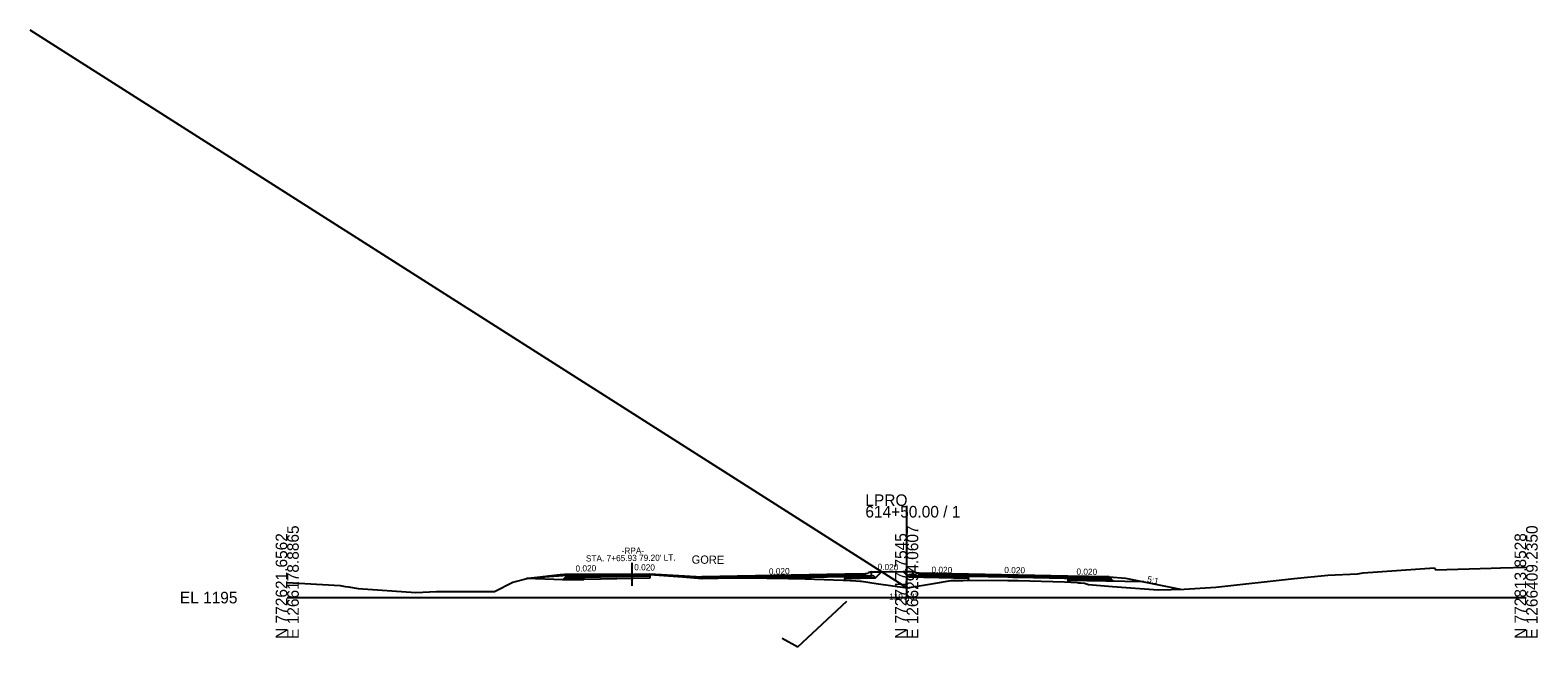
# Model space of a CAD drawing. Extents: x -3833 to 1267678, y -522 to 773248.
# Drawn here: x 1937.8 to 2302.8, y 5488.1 to 5637.4 of the extents above; entities that cross this region are included whole.
import ezdxf

# ---------------------------------------------------------------- set-up
doc = ezdxf.new("R2010")
doc.units = 0
for name, color, linetype in [('Exist Cross Section Cell', 7, 'Continuous'), ('Exist XS Center Line Elevation Label', 7, 'Continuous'), ('Exist XS Ground Line', 7, 'Continuous'), ('Prop CMT Corridor Surface Symbology Green', 7, 'Continuous'), ('Prop CMT DNC', 7, 'Continuous'), ('Prop CMT Pvmt Course 1', 7, 'Continuous'), ('Prop CMT Pvmt Course 2', 7, 'Continuous'), ('Prop CMT Pvmt Course 3', 7, 'Continuous'), ('Prop CMT Pvmt Course 4', 7, 'Continuous'), ('Prop CMT Shld Paved Course 1', 7, 'Continuous'), ('Prop CMT Shld Paved Course 2', 7, 'Continuous'), ('Prop CMT Shld Paved Course 4', 7, 'Continuous'), ('Prop CMT Slope Grass', 7, 'Continuous'), ('Prop CMT Subgrade Earthwork', 7, 'Continuous'), ('Prop Conc Curb and Gutter', 7, 'Continuous'), ('Prop Conc Island Cover', 7, 'Continuous'), ('Prop Corridor Mesh Bottom', 7, 'Continuous'), ('Prop XS Ditch Slope Text', 7, 'Continuous'), ('Prop XS Finish Grade', 7, 'Continuous'), ('Prop XS SE Text', 7, 'Continuous'), ('Prop XS Shear Point Element', 7, 'Continuous'), ('Prop XS Shear Point Label', 7, 'Continuous'), ('Scratch_Level_1', 7, 'Continuous'), ('Scratch_Level_5', 7, 'Continuous')]:
    doc.layers.add(name, color=color, linetype=linetype)

msp = doc.modelspace()

# ---------------------------------------------------------------- linework, layer by layer
at = {"layer": 'Exist Cross Section Cell'}
for p, q in [((2150, 5500), (2150, 5522.2)), ((2000, 5500), (2150, 5500)), ((2150, 5500), (2300, 5500))]:
    msp.add_line(p, q, dxfattribs=at)
at = {"layer": 'Exist XS Ground Line'}
for p, q in [((2058.41, 5504.72), (2066.11, 5505.59)), ((2066.11, 5505.59), (2067.15, 5505.7)), ((2067.15, 5505.7), (2073.18, 5505.68)), ((2073.18, 5505.68), (2083.57, 5505.64)), ((2083.57, 5505.64), (2086.45, 5505.51)), ((2087.18, 5505.49), (2087.86, 5505.61)), ((2087.86, 5505.61), (2088.94, 5505.52)), ((2252.01, 5505.42), (2259.15, 5505.75)), ((2259.15, 5505.75), (2260.55, 5505.96)), ((2260.55, 5505.96), (2277.79, 5507.22)), ((2277.79, 5507.22), (2278.16, 5506.71)), ((2278.16, 5506.71), (2291.56, 5507.14)), ((2291.56, 5507.14), (2293.8, 5507.21)), ((2293.8, 5507.21), (2300, 5507.4)), ((2000, 5503.66), (2012.83, 5502.97)), ((2012.83, 5502.97), (2014.07, 5502.67)), ((2014.07, 5502.67), (2014.8, 5502.62)), ((2014.8, 5502.62), (2017.17, 5502.19)), ((2017.17, 5502.19), (2031.11, 5501.2)), ((2050.17, 5501.49), (2054.61, 5503.71)), ((2054.61, 5503.71), (2058.41, 5504.72)), ((2086.45, 5505.51), (2087.18, 5505.49)), ((2088.94, 5505.52), (2095.68, 5505.01)), ((2095.68, 5505.01), (2100.49, 5504.63)), ((2100.49, 5504.63), (2108.21, 5504.78)), ((2108.21, 5504.78), (2111.02, 5504.82)), ((2111.02, 5504.82), (2121.35, 5504.62)), ((2121.35, 5504.62), (2123.05, 5504.6)), ((2123.05, 5504.6), (2134.66, 5504.19)), ((2134.66, 5504.19), (2136.33, 5504.13)), ((2136.33, 5504.13), (2136.67, 5504.11)), ((2136.67, 5504.11), (2138.74, 5504)), ((2138.74, 5504), (2139.09, 5503.95)), ((2139.09, 5503.95), (2142.64, 5503.44)), ((2142.64, 5503.44), (2150.11, 5502.36)), ((2150.11, 5502.36), (2156.95, 5503.51)), ((2156.95, 5503.51), (2160.27, 5504.05)), ((2160.27, 5504.05), (2160.75, 5504.14)), ((2160.75, 5504.14), (2163.68, 5504.18)), ((2163.68, 5504.18), (2164.03, 5504.19)), ((2164.03, 5504.19), (2174.51, 5504.16)), ((2174.51, 5504.16), (2175.71, 5504.15)), ((2175.71, 5504.15), (2176.99, 5504.11)), ((2176.99, 5504.11), (2188.24, 5503.79)), ((2188.24, 5503.79), (2191.31, 5503.62)), ((2191.31, 5503.62), (2191.64, 5503.59)), ((2191.64, 5503.59), (2192.12, 5503.56)), ((2192.12, 5503.56), (2193.04, 5503.46)), ((2193.04, 5503.46), (2194.01, 5503.16)), ((2194.01, 5503.16), (2199.82, 5502.72)), ((2199.82, 5502.72), (2210.9, 5501.85)), ((2210.9, 5501.85), (2217.18, 5502.05)), ((2217.18, 5502.05), (2224.87, 5502.53)), ((2224.87, 5502.53), (2243.83, 5504.65)), ((2243.83, 5504.65), (2252.01, 5505.42)), ((2031.11, 5501.2), (2036.18, 5501.45)), ((2036.18, 5501.45), (2050.17, 5501.49))]:
    msp.add_line(p, q, dxfattribs=at)
at = {"layer": 'Prop CMT Pvmt Course 1'}
for p, q in [((2071.83, 5505.46), (2083.83, 5505.7)), ((2083.83, 5505.7), (2087.83, 5505.78)), ((2083.83, 5505.7), (2083.83, 5505.7)), ((2087.83, 5505.53), (2083.83, 5505.45)), ((2087.83, 5505.78), (2100.42, 5505)), ((2087.83, 5505.78), (2087.83, 5505.53)), ((2087.83, 5505.78), (2087.83, 5505.78)), ((2087.83, 5505.78), (2087.83, 5505.78)), ((2087.83, 5505.53), (2087.83, 5505.53)), ((2135, 5505.69), (2100.42, 5505)), ((2135, 5505.44), (2135, 5505.69)), ((2189, 5505.21), (2165, 5505.69)), ((2165, 5505.69), (2165, 5505.44)), ((2071.83, 5505.21), (2071.83, 5505.46)), ((2071.83, 5505.46), (2071.83, 5505.46)), ((2083.83, 5505.45), (2071.83, 5505.21)), ((2083.83, 5505.45), (2083.83, 5505.45)), ((2100.42, 5504.75), (2135, 5505.44)), ((2100.42, 5505), (2100.42, 5505)), ((2100.42, 5505), (2100.42, 5504.75)), ((2100.42, 5504.75), (2100.42, 5504.75)), ((2135, 5505.44), (2135, 5505.44)), ((2165, 5505.44), (2165, 5505.44)), ((2165, 5505.44), (2189, 5504.96)), ((2189, 5504.96), (2189, 5505.21)), ((2189, 5505.21), (2189, 5505.21)), ((2189, 5504.96), (2189, 5504.96)), ((2189, 5504.96), (2189, 5504.96))]:
    msp.add_line(p, q, dxfattribs=at)
at = {"layer": 'Prop CMT Pvmt Course 2'}
for p, q in [((2083.83, 5505.45), (2087.83, 5505.53)), ((2087.83, 5505.53), (2087.83, 5505.28)), ((2087.83, 5505.53), (2087.83, 5505.53)), ((2087.83, 5505.53), (2087.83, 5505.53)), ((2087.84, 5505.6), (2100.42, 5504.75)), ((2139.96, 5505.54), (2135, 5505.44)), ((2165, 5505.44), (2153, 5505.68)), ((2071.83, 5505.21), (2083.83, 5505.45)), ((2071.83, 5504.96), (2071.83, 5505.21)), ((2071.83, 5505.21), (2071.83, 5505.21)), ((2083.83, 5505.45), (2083.83, 5505.45)), ((2083.83, 5505.2), (2083.83, 5505.2)), ((2087.83, 5505.2), (2083.84, 5505.12)), ((2087.83, 5505.28), (2087.83, 5505.28)), ((2135, 5505.44), (2135, 5505.44)), ((2135, 5505.44), (2135, 5505.11)), ((2135, 5505.1), (2139.96, 5505.2)), ((2135, 5505.11), (2135, 5505.11)), ((2135, 5505.11), (2135, 5505.1)), ((2135, 5505.1), (2135, 5505.1)), ((2153, 5505.35), (2165, 5505.1)), ((2165, 5505.44), (2165, 5505.44)), ((2165, 5505.1), (2165, 5505.1)), ((2165, 5505.1), (2165, 5505.1)), ((2165, 5505.1), (2165, 5505.1))]:
    msp.add_line(p, q, dxfattribs=at)
at = {"layer": 'Prop CMT Pvmt Course 3'}
for p, q in [((2141.97, 5505.24), (2139.96, 5505.2)), ((2139.96, 5505.2), (2139.96, 5505.2)), ((2142.42, 5504.8), (2141.97, 5505.24)), ((2150.7, 5505.1), (2150.99, 5505.38))]:
    msp.add_line(p, q, dxfattribs=at)
at = {"layer": 'Prop CMT Pvmt Course 4'}
for p, q in [((2067.23, 5504.79), (2071.84, 5504.88)), ((2071.83, 5504.46), (2071.83, 5504.96)), ((2071.83, 5504.96), (2071.83, 5504.96)), ((2083.85, 5504.66), (2071.83, 5504.42)), ((2083.84, 5505.12), (2071.84, 5504.88)), ((2083.83, 5505.2), (2083.83, 5505.2)), ((2087.83, 5504.74), (2083.85, 5504.66)), ((2087.83, 5505.28), (2087.83, 5504.74)), ((2087.83, 5505.28), (2087.83, 5505.28)), ((2087.83, 5505.28), (2087.83, 5505.28)), ((2087.83, 5504.78), (2087.83, 5504.78)), ((2139.96, 5505.2), (2135, 5505.1)), ((2135, 5505.1), (2135, 5505.11)), ((2135, 5505.11), (2135, 5504.18)), ((2135, 5505.1), (2135, 5505.1)), ((2135, 5504.64), (2142.42, 5504.8)), ((2135, 5504.27), (2135, 5504.27)), ((2135, 5504.27), (2135, 5504.27)), ((2135, 5504.27), (2135, 5504.27)), ((2150.99, 5505.38), (2150.54, 5504.94)), ((2151.49, 5505.37), (2150.99, 5505.38)), ((2165, 5504.27), (2165, 5505.1)), ((2165, 5505.1), (2165, 5505.1)), ((2165, 5505.1), (2165, 5505.1)), ((2165, 5504.27), (2165, 5504.27)), ((2165, 5504.27), (2165, 5504.27)), ((2165, 5504.27), (2165, 5504.27))]:
    msp.add_line(p, q, dxfattribs=at)
at = {"layer": 'Prop CMT Shld Paved Course 1'}
for p, q in [((2139.96, 5505.79), (2135, 5505.69)), ((2135, 5505.69), (2135, 5505.69)), ((2135, 5505.69), (2135, 5505.44)), ((2135, 5505.44), (2139.96, 5505.54)), ((2165, 5505.69), (2153, 5505.93)), ((2165, 5505.44), (2165, 5505.69)), ((2165, 5505.69), (2165, 5505.69)), ((2067.58, 5505.13), (2067.83, 5505.38)), ((2071.83, 5505.21), (2067.58, 5505.13)), ((2067.83, 5505.38), (2071.83, 5505.46)), ((2071.83, 5505.46), (2071.83, 5505.21)), ((2135, 5505.44), (2135, 5505.44)), ((2135, 5505.44), (2135, 5505.44)), ((2165, 5505.44), (2165, 5505.44)), ((2165, 5505.44), (2165, 5505.44)), ((2189, 5505.21), (2189, 5504.96)), ((2199, 5505.01), (2189, 5505.21)), ((2189, 5504.96), (2199.26, 5504.75)), ((2199.26, 5504.75), (2199, 5505.01))]:
    msp.add_line(p, q, dxfattribs=at)
at = {"layer": 'Prop CMT Shld Paved Course 2'}
for p, q in [((2067.23, 5504.79), (2067.58, 5505.13)), ((2067.58, 5505.13), (2071.83, 5505.21)), ((2071.83, 5505.21), (2071.83, 5504.88)), ((2111.02, 5504.96), (2100.42, 5504.75)), ((2100.42, 5504.75), (2100.42, 5504.64)), ((2100.42, 5504.64), (2100.42, 5504.64)), ((2100.42, 5504.64), (2100.49, 5504.63)), ((2100.49, 5504.63), (2108.21, 5504.78)), ((2108.21, 5504.78), (2111.02, 5504.82)), ((2121.35, 5505.16), (2111.02, 5504.96)), ((2111.02, 5504.96), (2111.02, 5504.96)), ((2111.02, 5504.82), (2111.02, 5504.82)), ((2111.02, 5504.82), (2116.11, 5504.73)), ((2116.11, 5504.73), (2121.35, 5504.83)), ((2116.11, 5504.73), (2116.11, 5504.73)), ((2123.05, 5505.2), (2121.35, 5505.16)), ((2121.35, 5505.16), (2121.35, 5505.16)), ((2121.35, 5504.83), (2123.05, 5504.86)), ((2121.35, 5504.83), (2121.35, 5504.83)), ((2134.66, 5505.43), (2123.05, 5505.2)), ((2123.05, 5505.2), (2123.05, 5505.2)), ((2123.05, 5504.86), (2134.66, 5505.1)), ((2123.05, 5504.86), (2123.05, 5504.86)), ((2135, 5505.44), (2134.66, 5505.43)), ((2134.66, 5505.43), (2134.66, 5505.43)), ((2134.66, 5505.1), (2134.66, 5505.1)), ((2134.66, 5505.1), (2135, 5505.1)), ((2135, 5505.1), (2135, 5505.44)), ((2135, 5505.1), (2135, 5505.1)), ((2165, 5505.1), (2165, 5505.44)), ((2165, 5505.44), (2165, 5505.44)), ((2165, 5505.44), (2174.51, 5505.25)), ((2174.51, 5504.91), (2165, 5505.1)), ((2165, 5505.1), (2165, 5505.1)), ((2165, 5505.1), (2165, 5505.1)), ((2174.51, 5505.25), (2174.51, 5505.25)), ((2174.51, 5505.25), (2175.71, 5505.22)), ((2175.71, 5504.89), (2174.51, 5504.91)), ((2174.51, 5504.91), (2174.51, 5504.91)), ((2175.71, 5505.22), (2176.99, 5505.2)), ((2176.99, 5504.86), (2175.71, 5504.89)), ((2176.99, 5505.2), (2176.99, 5505.2)), ((2176.99, 5505.2), (2188.24, 5504.97)), ((2188.24, 5504.64), (2176.99, 5504.86)), ((2176.99, 5504.86), (2176.99, 5504.86)), ((2188.24, 5504.97), (2188.24, 5504.97)), ((2188.24, 5504.97), (2189, 5504.96)), ((2189, 5504.62), (2188.24, 5504.64)), ((2188.24, 5504.64), (2188.24, 5504.64)), ((2189, 5504.96), (2189, 5504.96)), ((2189, 5504.96), (2189, 5504.62)), ((2189, 5504.96), (2189, 5504.63)), ((2199.26, 5504.75), (2189, 5504.96)), ((2189, 5504.63), (2199.59, 5504.41)), ((2189, 5504.62), (2189, 5504.62)), ((2189, 5504.62), (2189, 5504.62)), ((2199.59, 5504.41), (2199.26, 5504.75))]:
    msp.add_line(p, q, dxfattribs=at)
at = {"layer": 'Prop CMT Shld Paved Course 4'}
for p, q in [((2066.77, 5504.32), (2067.23, 5504.79)), ((2071.83, 5504.42), (2066.77, 5504.32)), ((2071.83, 5504.88), (2071.83, 5504.42)), ((2189, 5504.63), (2189, 5504.17)), ((2199.09, 5504.42), (2189, 5504.63)), ((2199.59, 5504.41), (2199.09, 5504.42)), ((2200.06, 5503.95), (2199.59, 5504.41))]:
    msp.add_line(p, q, dxfattribs=at)
at = {"layer": 'Prop CMT Slope Grass'}
for p, q in [((2141.47, 5506.22), (2142.43, 5506.23)), ((2142.43, 5506.23), (2143.88, 5506.25)), ((2149.16, 5506.33), (2151.49, 5506.36)), ((2067.83, 5505.38), (2057.94, 5504.59)), ((2199, 5505.01), (2203, 5504.69)), ((2203, 5504.69), (2207.43, 5503.8))]:
    msp.add_line(p, q, dxfattribs=at)
at = {"layer": 'Prop CMT Subgrade Earthwork'}
for p, q in [((2087.83, 5505.6), (2087.83, 5504.74)), ((2142.42, 5504.8), (2143.88, 5506.25)), ((2150.54, 5504.94), (2149.16, 5506.33)), ((2066.77, 5504.32), (2057.94, 5504.59)), ((2066.77, 5504.32), (2071.83, 5504.42)), ((2087.83, 5504.74), (2071.83, 5504.42)), ((2142.42, 5504.8), (2135, 5504.64)), ((2135, 5504.18), (2135, 5504.64)), ((2165, 5504.64), (2150.54, 5504.94)), ((2165, 5504.64), (2165, 5504.19)), ((2207.43, 5503.8), (2189, 5504.17)), ((2189, 5504.17), (2189, 5503.75))]:
    msp.add_line(p, q, dxfattribs=at)
at = {"layer": 'Prop Conc Curb and Gutter'}
for p, q in [((2140.7, 5505.8), (2139.96, 5505.79)), ((2139.96, 5505.79), (2139.96, 5505.79)), ((2139.96, 5505.79), (2139.96, 5505.2)), ((2139.96, 5505.79), (2139.96, 5505.79)), ((2140.71, 5505.8), (2140.7, 5505.8)), ((2141.46, 5506.21), (2140.71, 5505.97)), ((2140.71, 5505.97), (2140.71, 5505.97)), ((2140.71, 5505.97), (2140.71, 5505.8)), ((2141.47, 5506.22), (2141.46, 5506.21)), ((2141.47, 5506.2), (2141.47, 5506.22)), ((2141.47, 5505.23), (2141.47, 5506.2)), ((2152.25, 5506.11), (2151.49, 5506.36)), ((2151.49, 5506.36), (2151.49, 5505.37)), ((2152.25, 5505.94), (2152.25, 5506.11)), ((2152.25, 5506.11), (2152.25, 5506.11)), ((2153, 5505.93), (2152.25, 5505.94)), ((2152.25, 5505.94), (2152.25, 5505.94)), ((2153, 5505.34), (2153, 5505.93)), ((2153, 5505.93), (2153, 5505.93)), ((2139.96, 5505.2), (2141.45, 5505.23)), ((2139.96, 5505.2), (2139.96, 5505.2)), ((2139.96, 5505.2), (2139.96, 5505.2)), ((2139.96, 5505.2), (2139.96, 5505.2)), ((2141.45, 5505.23), (2141.47, 5505.23)), ((2151.49, 5505.37), (2151.49, 5505.37)), ((2151.49, 5505.37), (2153, 5505.34)), ((2153, 5505.34), (2153, 5505.34)), ((2153, 5505.34), (2153, 5505.34))]:
    msp.add_line(p, q, dxfattribs=at)
at = {"layer": 'Prop Conc Island Cover'}
for p, q in [((2141.47, 5505.97), (2141.47, 5506.22)), ((2151.49, 5506.36), (2151.49, 5506.36)), ((2151.49, 5506.36), (2151.49, 5506.36)), ((2151.49, 5506.11), (2151.49, 5506.11)), ((2151.49, 5506.11), (2151.49, 5506.11))]:
    msp.add_line(p, q, dxfattribs=at)
at = {"layer": 'Prop Corridor Mesh Bottom'}
for p, q in [((2135, 5505.69), (2135, 5505.44)), ((2165, 5505.69), (2165, 5505.44)), ((2189, 5505.21), (2189, 5504.96))]:
    msp.add_line(p, q, dxfattribs=at)
at = {"layer": 'Prop XS Finish Grade'}
for p, q in [((2143.88, 5506.25), (2149.16, 5506.33)), ((2151.49, 5506.36), (2151.49, 5506.36)), ((2207.43, 5503.8), (2216.33, 5502.02))]:
    msp.add_line(p, q, dxfattribs=at)
at = {"layer": 'Prop XS Shear Point Element'}
msp.add_line((2083.42, 5508.45), (2083.42, 5502.88), dxfattribs=at)
at = {"layer": 'Scratch_Level_1'}
msp.add_line((2150, 5502.37), (1937.75, 5637.43), dxfattribs=at)
at = {"layer": 'Scratch_Level_5'}
for p, q in [((2123.64, 5488.07), (2135.49, 5499.1)), ((2119.85, 5490.18), (2123.64, 5488.07))]:
    msp.add_line(p, q, dxfattribs=at)

# ---------------------------------------------------------------- texts
at = {"layer": 'Exist Cross Section Cell'}
for s, p in [('LPRO', (2140, 5522.2)), ('614+50.00 / 1', (2140, 5519.4)), ('EL 1195', (1974, 5498.6))]:
    msp.add_text(s, height=2.8, dxfattribs=at).set_placement(p)
for s, p in [('E 1266178.8865', (2002.8, 5490)), ('E 1266294.0607', (2152.8, 5490)), ('E 1266409.2350', (2302.8, 5490)), ('N 772621.6562', (2000, 5490)), ('N 772717.7545', (2150, 5490)), ('N 772813.8528', (2300, 5490))]:
    msp.add_text(s, height=2.8, rotation=90, dxfattribs=at).set_placement(p)
at = {"layer": 'Exist XS Center Line Elevation Label'}
msp.add_text('1197.37', height=1.5, dxfattribs=at).set_placement((2145.75, 5499.47))
at = {"layer": 'Prop CMT Corridor Surface Symbology Green'}
msp.add_text('X', height=0.00025, dxfattribs=at).set_placement((2083.83, 5505.7))
at = {"layer": 'Prop CMT DNC'}
for p in [(2135, 5505.69), (2135, 5505.69), (2140.71, 5505.8), (2152.25, 5505.94), (2165, 5505.69), (2165, 5505.69), (2111, 5505.21), (2189, 5505.21), (2189, 5505.21), (2199, 5505.01), (2210, 5503.29), (2250.49, 5505.27)]:
    msp.add_text('X', height=0.00025, dxfattribs=at).set_placement(p)
at = {"layer": 'Prop XS Ditch Slope Text'}
msp.add_text('5:1', height=1.5, rotation=347.6015, dxfattribs=at).set_placement((2208.13, 5503.8))
at = {"layer": 'Prop XS SE Text'}
for s, rotation, p in [("STA. 7+65.93 79.20' LT.", 0.5826, (2072.33, 5508.74)), ('-RPA-', 0.5826, (2080.98, 5510.6)), ('0.020', 1.397, (2069.83, 5506.28)), ('0.020', 358.8542, (2084.01, 5506.63)), ('0.020', 1.397, (2116.66, 5505.57)), ('0.020', 358.8542, (2142.95, 5506.7)), ('0.020', 358.8542, (2156, 5506.02)), ('0.020', 358.8542, (2173.63, 5505.95)), ('0.020', 358.8542, (2191.1, 5505.57))]:
    msp.add_text(s, height=1.5, rotation=rotation, dxfattribs=at).set_placement(p)
at = {"layer": 'Prop XS Shear Point Label'}
msp.add_text('GORE', height=2, rotation=359.5382, dxfattribs=at).set_placement((2097.93, 5508.22))

doc.saveas('drawing.dxf')
